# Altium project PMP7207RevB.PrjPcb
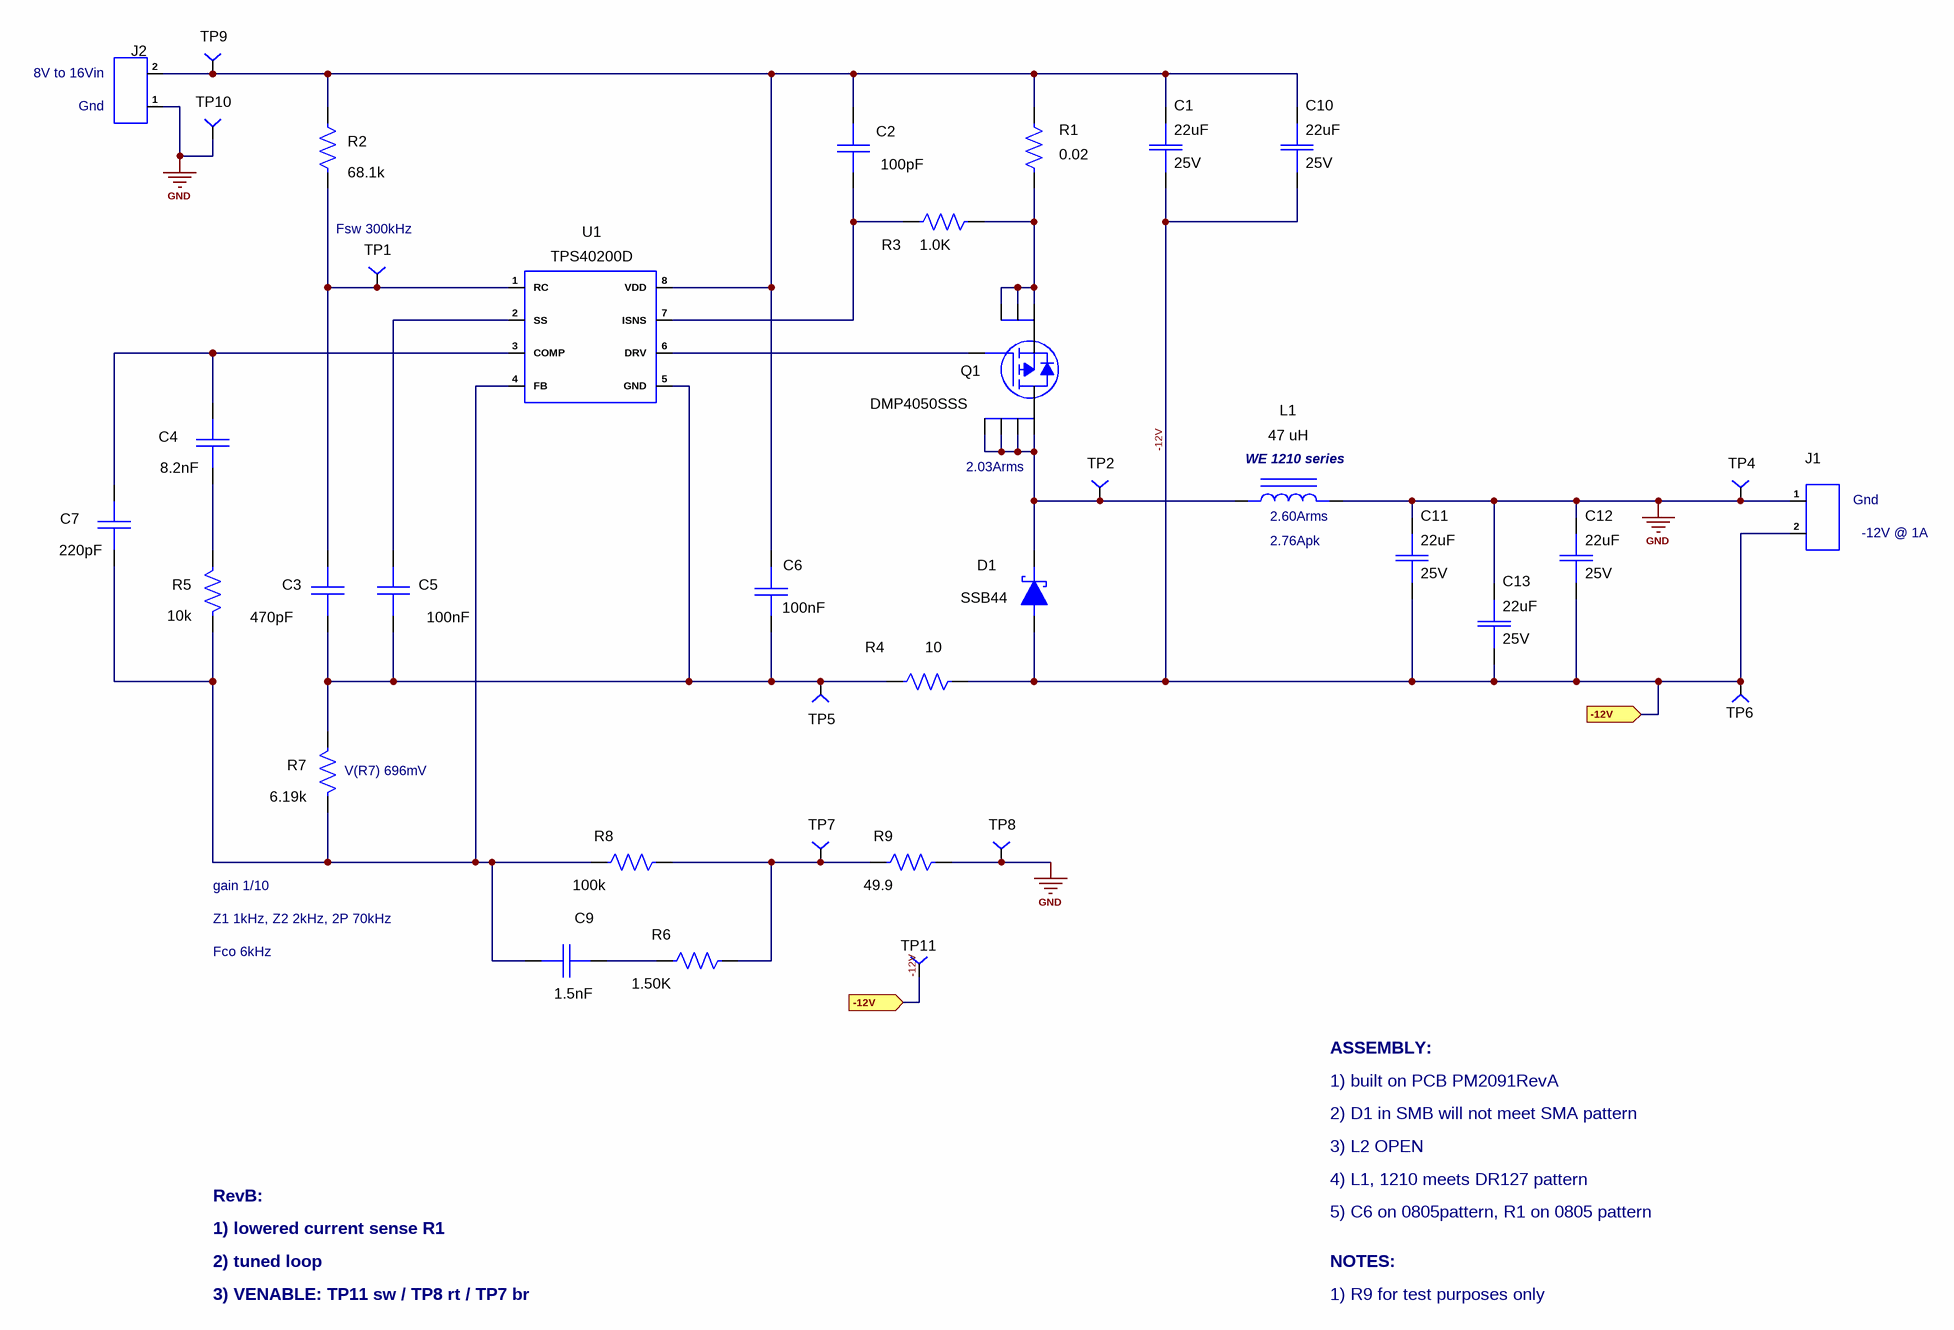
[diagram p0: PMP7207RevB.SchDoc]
PRJ_Engineer: B.Geck; PRJ_Number: PMP7207; PRJ_Title: Basic Inverting Buck Boost
1 sheet, 37 parts. Net scope: flat (ports and power ports of the same name join across sheets).

## Sheet PMP7207RevB.SchDoc: TPS40200, -12V inv. buckboost
size 431 x 279 mm; CompanyName: TEXAS INSTRUMENTS; Engineer: B.Geck; DocumentNumber: 1; Revision: B; SheetNumber: 1; SheetTotal: 1; SCH_Rev: B

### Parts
C1  value 22uF  Voltage: 25V  [C1210]  (hidden comment: C1210)
C2  value 100pF  [C603]  (hidden comment: C603)
C3  value 470pF  [C603]  (hidden comment: C603)
C4  value 8.2nF  [C603]  (hidden comment: C603)
C5  value 100nF  [C603]  (hidden comment: C603)
C6  value 100nF  [C603]  (hidden comment: C603)
C7  value 220pF  [C603]  (hidden comment: C603)
C9  value 1.5nF  [C603]  (hidden comment: C603)
C10  value 22uF  Voltage: 25V  [C1210]  (hidden comment: C1210)
C11  value 22uF  Voltage: 25V  [C1210]  (hidden comment: C1210)
C12  value 22uF  Voltage: 25V  [C1210]  (hidden comment: C1210)
C13  value 22uF  Voltage: 25V  [C1210]  (hidden comment: C1210)
D1  value SSB44  [MOT_SMB_CASE]  (hidden comment: D_SCHOT_SMB)
J1  TBLK_6A_2X3.5MM  [TB_2X3.5MM]  (value not drawn)
J2  TBLK_6A_2X3.5MM  [TB_2X3.5MM]  (value not drawn)
L1  value 47 uH  [IND_HC9]  (hidden comment: IND_HC9_SERIES)
Q1  value DMP4050SSS  [SO8]  (hidden comment: TR-FDS4435)
R1  value 0.02  [R1206]  (hidden comment: R1206_1%)
R2  value 68.1k  [R603]  (hidden comment: R603)
R3  value 1.0K  [R603]  (hidden comment: R603)
R4  value 10  [R603]  (hidden comment: R603)
R5  value 10k  [R603]  (hidden comment: R603)
R6  value 1.50K  [R603]  (hidden comment: R603)
R7  value 6.19k  [R603]  (hidden comment: R603)
R8  value 100k  [R603]  (hidden comment: R603)
R9  value 49.9  [R603]  (hidden comment: R603)
TP1  TP_RED_1MM  [TP_FARNELL_1MM]  (value not drawn)
TP2  TP_RED_1MM  [TP_FARNELL_1MM]  (value not drawn)
TP4  TP_RED_1MM  [TP_FARNELL_1MM]  (value not drawn)
TP5  TP_BLACK_1MM  [TP_FARNELL_1MM]  (value not drawn)
TP6  TP_BLACK_1MM  [TP_FARNELL_1MM]  (value not drawn)
TP7  TP_RED_1MM  [TP_FARNELL_1MM]  (value not drawn)
TP8  TP_RED_1MM  [TP_FARNELL_1MM]  (value not drawn)
TP9  TP_RED_1MM  [TP_FARNELL_1MM]  (value not drawn)
TP10  TP_RED_1MM  [TP_FARNELL_1MM]  (value not drawn)
TP11  TP_RED_1MM  [TP_FARNELL_1MM]  (value not drawn)
U1  TPS40200D  [SO8]

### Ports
-12V

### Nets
GND: C11.2 C12.2 C13.2 J1.1 J2.1 L1.2 R9.2 TP4.1 TP8.1 TP10.1
-12V: C1.1 C10.1 C11.1 C12.1 C13.1 D1.2(A) J1.2 R4.2 TP6.1 TP11.1 ; port -12V
NetC1_2: C1.2 C2.2 C6.2 C10.2 J2.2 R1.1 R2.1 TP9.1 U1.8(VDD)
NetC2_1: C2.1 R3.1 U1.7(ISNS)
NetC3_1: C3.1 R2.2 TP1.1 U1.1(RC)
NetC3_2: C3.2 C5.2 C6.1 R4.1 R7.1 TP5.1 U1.5(GND)
NetC4_1: C4.1 C7.1 U1.3(COMP)
NetC4_2: C4.2 R5.1
NetC5_1: C5.1 U1.2(SS)
NetC7_2: C7.2 C9.2 R5.2 R7.2 R8.1 U1.4(FB)
NetC9_1: C9.1 R6.1
NetD1_1: D1.1(C) L1.1 Q1.5(D) Q1.6(D) Q1.7(D) Q1.8(D) TP2.1
NetQ1_1: Q1.1(S) Q1.2(S) Q1.3(S) R1.2 R3.2
NetQ1_4: Q1.4(G) U1.6(DRV)
NetR6_2: R6.2 R8.2 R9.1 TP7.1

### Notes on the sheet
- (near J2) 8V to 16Vin
- (near J2) Gnd
- Fsw 300kHz
- (near Q1) 2.03Arms
- (near L1) WE 1210 series
- (near J1) Gnd
- (near L1) 2.76Apk
- (near L1) 2.60Arms
- (near J1) -12V @ 1A
- (near R7) V(R7) 696mV
- gain 1/10
- Z1 1kHz, Z2 2kHz, 2P 70kHz
- Fco 6kHz
- ASSEMBLY:
- 1) built on PCB PM2091RevA
- 2) D1 in SMB will not meet SMA pattern
- 3) L2 OPEN
- RevB:
- 1) lowered current sense R1
- 4) L1, 1210 meets DR127 pattern
- 5) C6 on 0805pattern, R1 on 0805 pattern
- 2) tuned loop
- 3) VENABLE: TP11 sw / TP8 rt / TP7 br
- NOTES:
- 1) R9 for test purposes only

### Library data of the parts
C1 C10-C13 = C1210: Capacitor, Ceramic, 25V, X7R, 15%; Manufacturer: Murata; PartNumber: GRM32ER71E226KE15L; Area: 28000; Second_Source: C:\program files\p-cad 2004\pcad_pdf's\TDK_e413_c.pdf
C2 = C603: Capacitor, Ceramic, 100-pF, 50-V, X7R, 15%; Manufacturer: TDK; PartNumber: Std; Area: 5650
C3 = C603: Capacitor, Ceramic, 470-pF, 50-V, X7R, 15%; Manufacturer: TDK; PartNumber: Std; Area: 5650
C4 = C603: Capacitor, Ceramic, 4700-pF, 50-V, X7R, 15%; Manufacturer: TDK; PartNumber: Std; Area: 5650
C5 = C603: Capacitor, Ceramic, 0.01-uF, 50-V, X7R, 15%; Manufacturer: TDK; PartNumber: Std; Area: 5650
C6 = C603: Capacitor, Ceramic, 0.1-uF, 50-V, X7R, 15%; Manufacturer: TDK; PartNumber: Std; Area: 5650
C7 = C603: Capacitor, Ceramic, 33-pF, 50-V, X7R, 15%; Manufacturer: TDK; PartNumber: Std; Area: 5650
C9 = C603: Capacitor, Ceramic, 50-V, X7R, 15%; Manufacturer: TDK; PartNumber: Std; Area: 5650
D1 = D_SCHOT_SMB: Diode, Schottky, 4-A, 40-V; PartNumber: STD; Manufacturer: Vishay; Area: 95000
J1 J2 = TBLK_6A_2X3.5MM: Terminal Block, 2-pin, 6-A, 3.5mm; PartNumber: ED1514; Manufacturer: OST; Area: 75525; Value: ED1514
L1 = IND_HC9_SERIES: Inductor, SMT,  3.8Arms, 45.9-milliohms; Manufacturer: Wuerth 1210 series; PartNumber: 7447709470; Second Source: C:\program files\p-cad 2004\pcad_pdf's\HC9 series.pdf; Area: 359100
Q1 = TR-FDS4435: MOSFET, Pch, -40V, -6A, 50-milliohm; Manufacturer: Diodes (Zetex); Second Source: C:\program files\p-cad 2004\pcad_pdf's\FDS4435.pdf; Area: 75900
R1 = R1206_1%: Resistor, Chip, 1/8W, 1%; PartNumber: CRCW1206-xxxx-F; Manufacturer: Vishay; Area: 20,000
R2 = R603: Resistor, Chip, 127K-Ohms, 1/16-W, 1%; PartNumber: Std; Area: 5650
R3 = R603: Resistor, Chip, 2.2-Ohms, 1/16-W, 1%; PartNumber: Std; Area: 5650
R4 = R603: Resistor, Chip, 0-Ohms, 1/16-W, 1%; PartNumber: Std; Area: 5650
R5 R8 = R603: Resistor, Chip, 100K-Ohms, 1/16-W, 1%; PartNumber: Std; Area: 5650
R6 = R603: Resistor, Chip, 1/16-W, 1%; PartNumber: Std; Area: 5650
R7 = R603: Resistor, Chip, 26.7K-Ohms, 1/16-W, 1%; PartNumber: Std; Area: 5650
R9 = R603: Resistor, Chip, 49.9-Ohms, 1/16-W, 1%; PartNumber: Std; Area: 5650
TP1 TP2 TP4 TP7-TP11 = TP_RED_1MM: Test Point, Red, 1mm; Manufacturer: Farnell; PartNumber: 240-345; Area: 6400
TP5 TP6 = TP_BLACK_1MM: Test Point, Black, 1mm; PartNumber: 240-333; Manufacturer: Farnell; Area: 6400
U1 = TPS40200D: IC, Low Cost Sync Buck Controller; Manufacturer: TI; Alternate Manufacturer: None; Area: 75,900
